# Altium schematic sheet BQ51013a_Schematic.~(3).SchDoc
size A
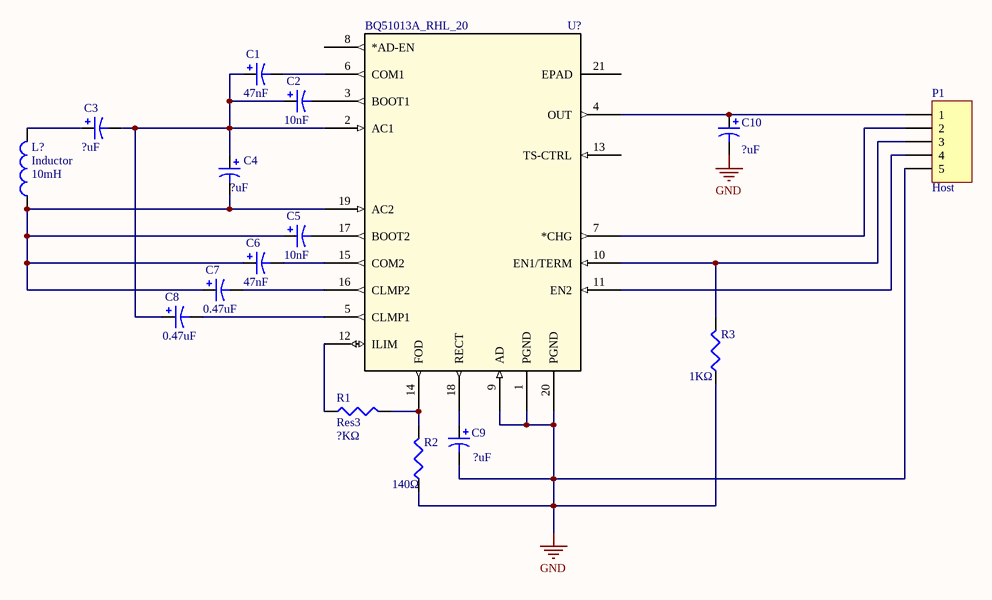
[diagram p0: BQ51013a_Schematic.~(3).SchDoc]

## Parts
C1  value 47nF  [C0805]
C2  value 10nF  [C0805]
C3  value ?uF  [C0805]
C4  value ?uF  [C0805]
C5  value 10nF  [C0805]
C6  value 47nF  [C0805]
C7  value 0.47uF  [C0805]
C8  value 0.47uF  [C0805]
C9  value ?uF  [C0805]
C10  value ?uF  [C0805]
L?  Inductor  value 10mH  [0402-A]
P1  Host  [MHDR1X5]
R1  Res3  value ?KΩ  [J1-0603]
R2  value 140Ω  [J1-0603]
R3  value 1KΩ  [J1-0603]
U?  BQ51013A_RHL_20  [RHL20_2P05X3P05]

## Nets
GND: C9.2 C10.2 P1.5 R2.1 R3.1 U?.1(PGND) U?.9(AD) U?.20(PGND)
NetC1_1: C1.1 C2.1 C3.2 C4.1 C8.1 U?.2(AC1)
NetC1_2: C1.2 U?.6(COM1)
NetC2_2: C2.2 U?.3(BOOT1)
NetC3_1: C3.1 L?.2
NetC4_2: C4.2 C5.1 C6.1 C7.1 L?.1 U?.19(AC2)
NetC5_2: C5.2 U?.17(BOOT2)
NetC6_2: C6.2 U?.15(COM2)
NetC7_2: C7.2 U?.16(CLMP2)
NetC8_2: C8.2 U?.5(CLMP1)
NetC9_1: C9.1 U?.18(RECT)
NetC10_1: C10.1 P1.1 U?.4(OUT)
NetP1_2: P1.2 U?.7(*CHG)
NetP1_3: P1.3 R3.2 U?.10(EN1/TERM)
NetP1_4: P1.4 U?.11(EN2)
NetR1_1: R1.1 U?.12(ILIM)
NetR1_2: R1.2 R2.2 U?.14(FOD)

Not connected (* = marked no-connect by the designer): U? 8(*AD-EN) 13(TS-CTRL) 21(EPAD)

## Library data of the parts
C1-C10 = Cap Pol3: Polarized Capacitor (Surface Mount)
L? = Inductor: Code_IEC: 1005
P1 = MHDR1X5: Header, 5-Pin
R1-R3 = Res3: Resistor
U? = BQ51013A_RHL_20: Imported; Vendor: TEXAS INSTRUMENTS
